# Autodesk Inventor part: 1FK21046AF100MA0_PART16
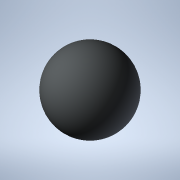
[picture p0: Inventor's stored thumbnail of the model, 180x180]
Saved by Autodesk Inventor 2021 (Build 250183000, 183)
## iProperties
Created: 2025-04
Part Number: 1FK21046AF100MA0_PART16
Material: Generic
Catalog Web Link: www.3dfindit.com
Description: -Servo synchronous motor
Document SubType Name: Modeling
Designer: psAdmin
Mass: 0.137258 g
Surface Area: 1.2868 cm^2
Volume: 0.137258 cm^3
Density: 1 g/cm^3
Appearance: PSOLRGB-212-217-219
Category: PARTsolutions
Title: 1FK21046AF100MA0_PART16
Author: Cadenas PARTsolutions
Comments: Servo synchronous motor
Sending System: PARTsolutions
Preprocessor: ST-DEVELOPER v19.3
PSOL_IDENT_0: {$CADENAS_DATA/23d-libs/siemens_ag/_cat_/4f/2b/1fk21046af100ma0.prj},216 {VTYP=3D},{NB=1FK21046AF100
PSOL_IDENT_1: MA0_PART16},{LINA=1FK21046AF100MA0_PART16},{NN=1FK21046AF100MA0_PART16},{NOPRJ=TRUE},{DATE=19.08.202
PSOL_IDENT_2: 5 14:00:37},{GEOMDATE=30.07.2025 02:01:06},{VERSION=},{LINEID=10},{WBVAR=},{WBNUMERIC=}  {NB=1FK2104
PSOL_IDENT_3: 6AF100MA0_PART16},{LINA=1FK21046AF100MA0_PART16},{KT=DUMMY},{PREVIEW=../../../_pool_/cb/72/p_d211_xx
PSOL_IDENT_4: _00434j.png},{DESCSHORT=SIMOTICS S-1FK2 HD, SINAMICS S210 3AC 400V-480V, 3.2 Nm, 3000 rpm},{DESCLONG=
PSOL_IDENT_5: SIMOTICS S-1FK2 HD servo motor M0=3.2 Nm; PN = 1 kW at nN=3000 rpm (380-480 V); PN = 0.5 kW at nN=15
PSOL_IDENT_6: 00 rpm (200-240 V); with holding brake; degree of protection IP64; cylindrical shaft D19x40mm; absol
PSOL_IDENT_7: ute encoder 22-bit + 12-bit multiturn (encoder AM22DQC); with OCC interface; plug size M17, rotatabl
PSOL_IDENT_8: e; SIMOTICS S-1FK2 servomotorfor a wide range of uses in industrial environments. SIMOTICS S‑1FK2 se
PSOL_IDENT_9: rvomotors are compact synchronous motors with a high dynamic performance that set themselves apart a
PSOL_IDENT_10: s a result of their high power density, degree of protection and overload capability. The motors are
PSOL_IDENT_11: available in two variants: as High Dynamic variant (highest dynamic performance as a result of the
PSOL_IDENT_12: low intrinsic moment of inertia for applications demanding a high dynamic performance with low moved
PSOL_IDENT_13: masses) - and as Compact variant (precise and stable closed-loop control for medium up to large mov
PSOL_IDENT_14: ed masses as a result of a medium intrinsic moment of inertia). SIMOTICSS‑1FK2 servomotors fully exp
PSOL_IDENT_15: loit their strengths in a system with the SINAMICSS210 frequency converter and simple connection usi
PSOL_IDENT_16: ng the one cable connection (OCC). Advantages include the short control and positioning times, fast
PSOL_IDENT_17: and precise correction of disturbing quantities as well as stable control with a high dynamic perfor
PSOL_IDENT_18: mance. The servo motors can be configured to address a wide range of requirements. For example with
PSOL_IDENT_19: and without holding brake, IP64 or IP65 degree of protection, singleturn or multiturn absolute encod
PSOL_IDENT_20: ers - to name just a few. Further, the servomotors are available in different shaft heights extendin
PSOL_IDENT_21: g from 20 to 100. A shaft sealing ring is available to achieve an IP65 degree of protection and for
PSOL_IDENT_22: subsequent mounting at the motor or as spare part. SIMOTICS - the optimum motor for each and every m
PSOL_IDENT_23: otion control application.},{INTNO=195125049673},{SUPPLIERALTNO=1FK2104-6AF10-0MA0},{MANUID=1FK21046
PSOL_IDENT_24: AF100MA0},{MANUNAME=Siemens},{MANUTYPEDESC=Synchronous motor 1FK2-HD 3.2 NM},{AAU732=SIMOTICS},{AAO0
PSOL_IDENT_25: 57=S-1FK2},{AAU734=SIMOTICS S-1FK2 HD servo motor M0=3.2 Nm; PN = 1 kW at nN=3000 rpm (380-480 V); P
PSOL_IDENT_26: N = 0.5 kW at nN=1500 rpm (200-240 V); with holding brake; degree of protection IP64; cylindrical sh
PSOL_IDENT_27: aft D19x40mm; absolute encoder 22-bit + 12-bit multiturn (encoder AM22DQC); with OCC interface; plug
PSOL_IDENT_28: size M17, rotatable;},{AAW338=Synchronous motor 1FK2-HD 3.2 NM},{AAO742=SIMOTICS},{AAO663=404294869
PSOL_IDENT_29: 4534},{NOCUPEROU=1},{PRICEQUANTITY=1},{QUANTITYMIN=1},{QUANTITYINT=1},{CTN=85015220},{COO=DE},{AAO67
PSOL_IDENT_30: 6=1FK2104-6AF10-0MA0},{AAO677=Siemens AG},{ORDERUNIT=C62},{CONTENTUNIT=C62}
NB: 1FK21046AF100MA0_PART16
NT: Servo synchronous motor
NBSYN: $MANUID._PART16
LINA: 1FK21046AF100MA0_PART16
CATALOG: SIEMENS
PREVIEW: ../../../_pool_/cb/72/p_d211_xx_00434j.png
DESCSHORT: SIMOTICS S-1FK2 HD, SINAMICS S210 3AC 400V-480V, 3.2 Nm, 3000 rpm
DESCLONG: SIMOTICS S-1FK2 HD servo motor M0=3.2 Nm; PN = 1 kW at nN=3000 rpm (380-480 V); PN = 0.5 kW at nN=1500 rpm (200-240 V); with holding brake; degree of protection
INTNO: 195125049673
SUPPLIERALTNO: 1FK2104-6AF10-0MA0
MANUID: 1FK21046AF100MA0
MANUNAME: Siemens
MANUTYPEDESC: Synchronous motor 1FK2-HD 3.2 NM
AAU732: SIMOTICS
AAO057: S-1FK2
AAU734: SIMOTICS S-1FK2 HD servo motor M0=3.2 Nm; PN = 1 kW at nN=3000 rpm (380-480 V); PN = 0.5 kW at nN=1500 rpm (200-240 V); with holding brake; degree of protection
AAW338: Synchronous motor 1FK2-HD 3.2 NM
AAO742: SIMOTICS
AAO663: 4042948694534.0
NOCUPEROU: 1
PRICEQUANTITY: 1
QUANTITYMIN: 1
QUANTITYINT: 1
CTN: 85015220
COO: DE
ARTICLENO: 1FK21046AF100MA0_PART16
BOMINFO: 1FK21046AF100MA0_PART16
CREATOR: CADENAS GmbH
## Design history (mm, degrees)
feature "2025_04_17_14_59_39_0177"
body "Solid1"
